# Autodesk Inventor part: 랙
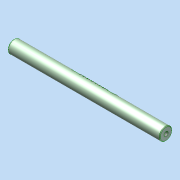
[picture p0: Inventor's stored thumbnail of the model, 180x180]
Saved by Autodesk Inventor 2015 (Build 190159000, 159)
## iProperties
Created: 2024-06
Part Number: 랙
Material: 일반
Document SubType Name: Modeling
Designer: Administrator
Density: 1 g/cm^3
Appearance: 기본값
Author: Administrator
Author: jhkim
Creation Date: 2024-05-29
Sending System: Autodesk Inventor 2025
Preprocessor: ST-DEVELOPER v20
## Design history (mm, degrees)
node "랙1"
node "솔리드1"
node "기준1"
